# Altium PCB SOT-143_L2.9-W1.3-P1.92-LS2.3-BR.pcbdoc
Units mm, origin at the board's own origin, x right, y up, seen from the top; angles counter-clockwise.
Board outline 15.6 x 16.16 mm, 2 copper layers (Top Layer, Bottom Layer), stack 0 mm thick; 1 components, 0 nets, 4 pads, 0 vias.
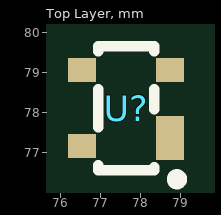
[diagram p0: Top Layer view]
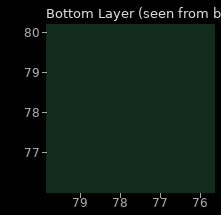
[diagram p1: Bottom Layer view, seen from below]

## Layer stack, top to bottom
Top Layer: signal copper (thickness not stored)
Bottom Layer: signal copper (thickness not stored)

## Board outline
85.45,69.85 69.85,69.85 69.85,86.005 85.45,86.005

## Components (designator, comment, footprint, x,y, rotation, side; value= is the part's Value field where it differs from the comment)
U? "" SOT-143_L2.9-W1.3-P1.92-LS2.3-BR 77.65,78.105 r0 top

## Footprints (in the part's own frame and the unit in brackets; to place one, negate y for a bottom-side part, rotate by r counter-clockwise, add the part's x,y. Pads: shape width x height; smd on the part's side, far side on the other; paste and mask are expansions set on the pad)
SOT-143_L2.9-W1.3-P1.92-LS2.3-BR [mm]
  rect 0.7x1.1 smd: 1(1.1,-0.75)
  rect 0.7x0.6 smd: 2(1.1,0.95) 3(-1.1,0.95) 4(-1.1,-0.95)
  silkscreen extent -0.7,-1.91 1.4,1.55

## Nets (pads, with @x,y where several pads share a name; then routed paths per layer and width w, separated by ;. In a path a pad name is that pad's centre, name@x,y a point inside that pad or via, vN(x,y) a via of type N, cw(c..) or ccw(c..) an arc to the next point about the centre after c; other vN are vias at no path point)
pads on no net: U?.1 U?.2 U?.3 U?.4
